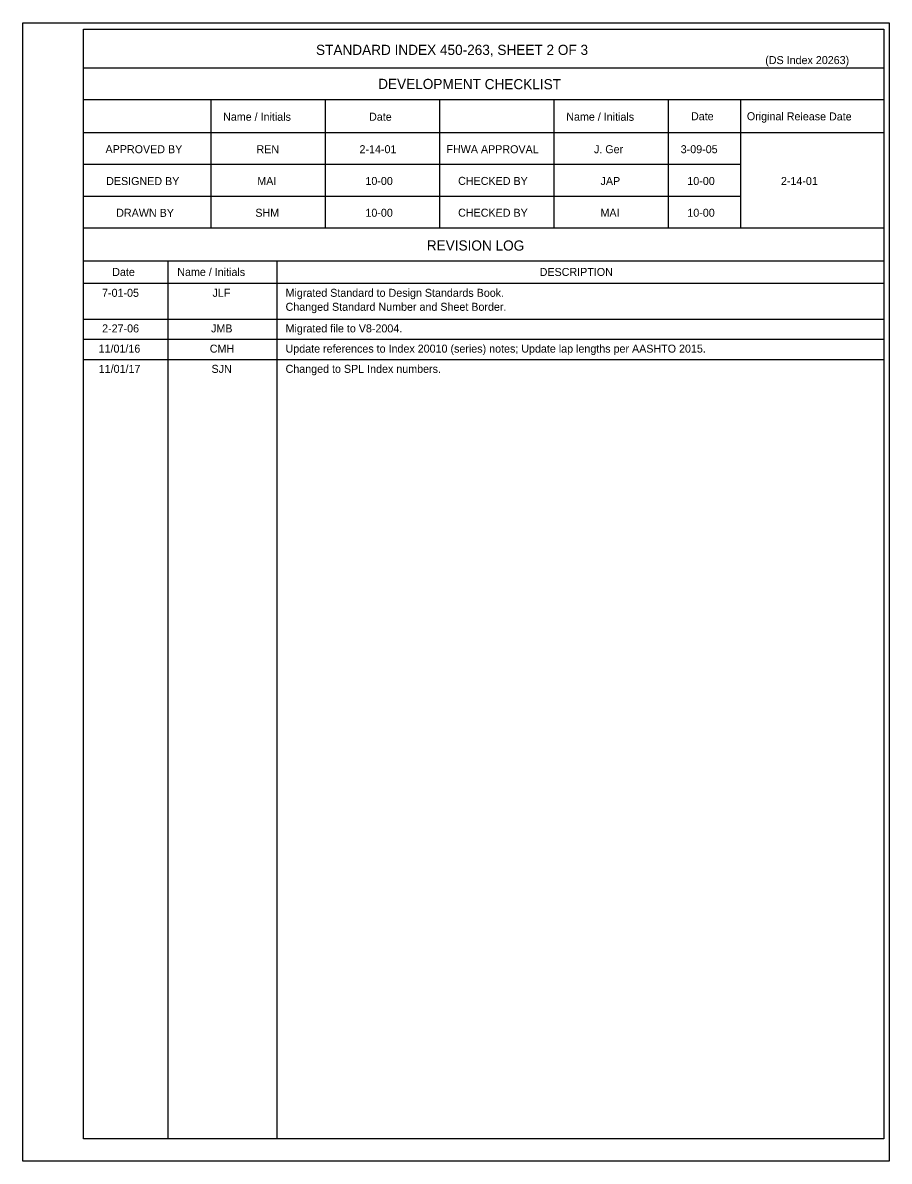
# Model space of a CAD drawing. Extents: x 120700.3 to 120754.4, y 120608.4 to 120631.3.
# Drawn here: x 120738.01 to 120754.37, y 120608.39 to 120629.89 of the extents above; entities that cross this region are included whole.
import ezdxf

# ---------------------------------------------------------------- set-up
doc = ezdxf.new("R2010")
doc.units = 0
for name, color, linetype in [('Border', 7, 'Continuous'), ('Dimension', 7, 'Continuous'), ('PlotBorder_dp', 7, 'Continuous'), ('TextStructures', 7, 'Continuous')]:
    doc.layers.add(name, color=color, linetype=linetype)

msp = doc.modelspace()

# ---------------------------------------------------------------- linework, layer by layer
at = {"layer": 'Border'}
for p, q in [((120754.264, 120629.032), (120739.154, 120629.032)), ((120754.264, 120628.432), (120739.154, 120628.432)), ((120741.554, 120628.432), (120741.554, 120626.011)), ((120743.714, 120628.432), (120743.714, 120626.011)), ((120745.874, 120628.432), (120745.874, 120626.011)), ((120748.034, 120628.432), (120748.034, 120626.011)), ((120750.194, 120628.432), (120750.194, 120626.011)), ((120751.555, 120628.432), (120751.555, 120626.011)), ((120754.264, 120627.811), (120739.154, 120627.811)), ((120751.555, 120627.211), (120739.154, 120627.211)), ((120751.555, 120626.611), (120739.154, 120626.611)), ((120754.264, 120626.011), (120739.154, 120626.011)), ((120754.264, 120625.39), (120739.154, 120625.39)), ((120740.744, 120625.39), (120740.744, 120608.811)), ((120742.801, 120625.39), (120742.801, 120608.811)), ((120754.264, 120624.968), (120739.154, 120624.968))]:
    msp.add_line(p, q, dxfattribs=at)
msp.add_lwpolyline([(120739.154, 120629.768), (120754.264, 120629.768), (120754.264, 120608.811), (120739.154, 120608.811)], close=True, dxfattribs=at)
at = {"layer": 'Dimension'}
for p, q in [((120739.154, 120624.295), (120754.264, 120624.295)), ((120739.154, 120623.913), (120754.264, 120623.913)), ((120739.154, 120623.531), (120754.264, 120623.531))]:
    msp.add_line(p, q, dxfattribs=at)
at = {"layer": 'PlotBorder_dp'}
msp.add_line((120738.006, 120608.39), (120738.006, 120608.39), dxfattribs=at)
msp.add_lwpolyline([(120738.006, 120629.89), (120754.366, 120629.89), (120754.366, 120608.39), (120738.006, 120608.39)], close=True, dxfattribs=at)

# ---------------------------------------------------------------- texts
at = {"layer": 'TextStructures'}
for s, height, p in [('STANDARD INDEX 450-263, SHEET 2 OF 3', 0.192, (120743.543, 120629.282)), ('(DS Index 20263)', 0.1512, (120752.025, 120629.109)), ('REN', 0.1512, (120742.418, 120627.426)), ('2-14-01', 0.1512, (120744.364, 120627.426)), ('J. Ger', 0.1512, (120748.791, 120627.426)), ('3-09-05', 0.1512, (120750.429, 120627.426)), ('MAI', 0.1512, (120742.434, 120626.826)), ('10-00', 0.1512, (120744.476, 120626.826)), ('JAP', 0.1512, (120748.915, 120626.826)), ('10-00', 0.1512, (120750.554, 120626.826)), ('2-14-01', 0.1512, (120752.321, 120626.826)), ('SHM', 0.1512, (120742.397, 120626.226)), ('10-00', 0.1512, (120744.476, 120626.226)), ('MAI', 0.1512, (120748.914, 120626.226)), ('10-00', 0.1512, (120750.554, 120626.226)), ('DESCRIPTION', 0.1512, (120747.766, 120625.108)), ('7-01-05', 0.1512, (120739.503, 120624.714)), ('JLF', 0.1512, (120741.589, 120624.714)), ('Migrated Standard to Design Standards Book.', 0.1512, (120742.968, 120624.714)), ('Changed Standard Number and Sheet Border.', 0.1512, (120742.968, 120624.45)), ('2-27-06', 0.1512, (120739.504, 120624.042)), ('JMB', 0.1512, (120741.561, 120624.042)), ('Migrated file to V8-2004.', 0.1512, (120742.968, 120624.042)), ('11/01/16', 0.1512, (120739.438, 120623.66)), ('CMH', 0.1512, (120741.537, 120623.66)), ('Update references to Index 20010 (series) notes; Update lap lengths per AASHTO 2015.', 0.1512, (120742.968, 120623.66)), ('11/01/17', 0.1512, (120739.44, 120623.278)), ('SJN', 0.1512, (120741.57, 120623.278)), ('Changed to SPL Index numbers.', 0.1512, (120742.968, 120623.278))]:
    msp.add_text(s, height=height, dxfattribs=at).set_placement(p)
for s, height, p in [('DEVELOPMENT CHECKLIST', 0.192, (120744.716, 120628.64)), ('Name / Initials', 0.1512, (120741.788, 120628.041)), ('Date', 0.1512, (120744.544, 120628.04)), ('Name / Initials', 0.1512, (120748.268, 120628.041)), ('Date', 0.1512, (120750.623, 120628.049)), ('Original Release Date', 0.1512, (120751.678, 120628.049)), ('APPROVED BY', 0.1512, (120739.568, 120627.428)), ('FHWA APPROVAL', 0.1512, (120746.005, 120627.428)), ('DESIGNED BY', 0.1512, (120739.58, 120626.826)), ('CHECKED BY', 0.1512, (120746.226, 120626.828)), ('DRAWN BY', 0.1512, (120739.77, 120626.226)), ('CHECKED BY', 0.1512, (120746.226, 120626.228)), ('REVISION LOG', 0.192, (120745.634, 120625.59)), ('Date', 0.1512, (120739.695, 120625.108)), ('Name / Initials', 0.1512, (120740.923, 120625.109))]:
    msp.add_text(s, height=height, rotation=359.8756, dxfattribs=at).set_placement(p)

doc.saveas('drawing.dxf')
